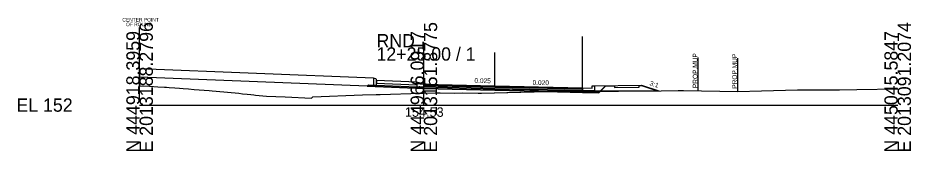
# Model space of a CAD drawing. Extents: x -26 to 163, y -10 to 7518.
# Drawn here: x -25.7 to 162.8, y 4490.3 to 4518.4 of the extents above; entities that cross this region are included whole.
import ezdxf

# ---------------------------------------------------------------- set-up
doc = ezdxf.new("R2010")
doc.units = 0
for name, color, linetype in [('Exist Cross Section Cell', 7, 'Continuous'), ('Exist XS Center Line Elevation Label', 7, 'Continuous'), ('Exist XS Ground Line', 7, 'Continuous'), ('Prop CMT Conc Surface', 7, 'Continuous'), ('Prop CMT Concrete Structures', 7, 'Continuous'), ('Prop CMT Pvmt Course 1', 7, 'Continuous'), ('Prop CMT Pvmt Course 1 CG', 7, 'Continuous'), ('Prop CMT Pvmt Course 2', 7, 'Continuous'), ('Prop CMT Pvmt Course 3', 7, 'Continuous'), ('Prop CMT Pvmt Surface', 7, 'Continuous'), ('Prop CMT Shear Line', 7, 'Continuous'), ('Prop CMT Shear Line Text', 7, 'Continuous'), ('Prop CMT Slope Grass', 7, 'Continuous'), ('Prop CMT Subgrade Earthwork', 7, 'Continuous'), ('Prop XS Earthwork Shape', 7, 'Continuous'), ('Prop XS Label Text', 7, 'Continuous'), ('Prop XS SE Text', 7, 'Continuous'), ('Prop XS Side Slope Text', 7, 'Continuous'), ('Scratch_Level_1', 7, 'Continuous')]:
    doc.layers.add(name, color=color, linetype=linetype)

msp = doc.modelspace()

# ---------------------------------------------------------------- linework, layer by layer
at = {"layer": 'Exist Cross Section Cell'}
for p, q in [((60, 4500), (60, 4512.16)), ((0, 4500), (60, 4500)), ((60, 4500), (160, 4500))]:
    msp.add_line(p, q, dxfattribs=at)
at = {"layer": 'Exist XS Ground Line'}
msp.add_lwpolyline([(0, 4504.05), (2.12, 4503.95), (3.88, 4503.85), (5.26, 4503.77), (5.67, 4503.74), (6.21, 4503.71), (7.45, 4503.63), (8.39, 4503.57), (9.23, 4503.5), (10.33, 4503.4), (11.52, 4503.3), (14.66, 4503.05), (15.33, 4502.99), (17.8, 4502.78), (18.56, 4502.71), (20.94, 4502.48), (21.7, 4502.39), (22.68, 4502.29), (23.49, 4502.21), (24.11, 4502.14), (24.47, 4502.11), (26.81, 4501.86), (30.69, 4501.71), (36.25, 4501.44), (36.55, 4501.77), (47.05, 4502.13), (49.93, 4502.24), (50.76, 4502.26), (59.46, 4502.52), (60, 4502.53), (62.37, 4502.57), (63.41, 4502.58), (66.44, 4502.54), (68.12, 4502.55), (71.45, 4502.54), (72.15, 4502.53), (86.04, 4502.86), (88.5, 4502.93), (98.29, 4502.93), (101.09, 4502.9), (110.08, 4503.02), (113.67, 4503.05), (114.78, 4503.04), (126.25, 4502.86), (131.26, 4502.97), (138.83, 4503.18), (147.75, 4503.22), (151.41, 4503.27), (160, 4503.43)], dxfattribs=at)
at = {"layer": 'Prop CMT Conc Surface'}
for points in [[(50, 4505.37), (49.96, 4505.47), (49.85, 4505.52), (49.34, 4505.7)], [(50, 4505.2), (50, 4505.37)], [(60, 4504.41), (59.25, 4504.43), (59.25, 4504.59), (58.5, 4504.84)], [(93.5, 4503.66), (95.49, 4503.53)], [(95.49, 4503.53), (95.5, 4504.03), (95.99, 4504.03)]]:
    msp.add_lwpolyline(points, dxfattribs=at)
at = {"layer": 'Prop CMT Concrete Structures'}
for points in [[(50, 4505.37), (49.96, 4505.47), (49.85, 4505.52), (49.34, 4505.7)], [(49.34, 4505.7), (49.34, 4504.2)], [(49.34, 4504.2), (50, 4504.2)], [(50, 4505.2), (50, 4505.37)], [(50, 4504.2), (50, 4505.2)], [(50, 4505.2), (50, 4504.62)], [(58.5, 4504.84), (50, 4505.19)], [(50, 4504.6), (58.5, 4504.26)], [(60, 4504.41), (59.25, 4504.43), (59.25, 4504.59), (58.5, 4504.84)], [(58.5, 4504.84), (58.5, 4503.86)], [(58.5, 4504.26), (58.5, 4504.84)], [(60, 4503.83), (60, 4504.41)], [(58.5, 4503.86), (60, 4503.83)], [(93.5, 4503.66), (95.49, 4503.53), (95.5, 4504.03), (95.99, 4504.03)], [(95.99, 4504.03), (95.99, 4503.01), (93.5, 4503.08)], [(93.5, 4503.08), (93.5, 4503.66)]]:
    msp.add_lwpolyline(points, dxfattribs=at)
at = {"layer": 'Prop CMT Pvmt Course 1'}
for points in [[(60, 4504.41), (75, 4504.03)], [(60, 4504.16), (60, 4504.41)], [(75, 4503.78), (60, 4504.16)], [(75, 4504.03), (93.5, 4503.66)], [(93.5, 4503.41), (75, 4503.78)], [(93.5, 4503.66), (93.5, 4503.41)]]:
    msp.add_lwpolyline(points, dxfattribs=at)
msp.add_lwpolyline([(60, 4504.16), (60, 4504.28), (60, 4504.28), (60, 4504.16)], close=True, dxfattribs=at)
at = {"layer": 'Prop CMT Pvmt Course 1 CG'}
for points in [[(60, 4503.49), (60, 4503.83)], [(93.5, 4503.08), (96.49, 4503), (96.83, 4502.66)], [(93.5, 4502.74), (93.5, 4503.08)], [(96.92, 4502.66), (93.5, 4502.74)]]:
    msp.add_lwpolyline(points, dxfattribs=at)
at = {"layer": 'Prop CMT Pvmt Course 2'}
for points in [[(60, 4503.83), (60, 4504.16)], [(60, 4504.16), (75, 4503.78)], [(75, 4503.45), (60, 4503.83)], [(75, 4503.78), (93.5, 4503.41)], [(93.51, 4503.08), (75, 4503.45)], [(93.5, 4503.41), (93.5, 4503.08)]]:
    msp.add_lwpolyline(points, dxfattribs=at)
at = {"layer": 'Prop CMT Pvmt Course 3'}
for points in [[(50, 4504.2), (58.5, 4503.86)], [(60, 4503.83), (75, 4503.45)], [(60, 4503.49), (60, 4503.83)], [(75, 4503.11), (60, 4503.49)], [(75, 4503.45), (93.51, 4503.08)], [(93.51, 4502.74), (75, 4503.11)], [(93.5, 4503.08), (93.5, 4502.74)]]:
    msp.add_lwpolyline(points, dxfattribs=at)
at = {"layer": 'Prop CMT Pvmt Surface'}
for points in [[(60, 4504.41), (75, 4504.03)], [(75, 4504.03), (93.5, 4503.66)]]:
    msp.add_lwpolyline(points, dxfattribs=at)
at = {"layer": 'Prop CMT Shear Line'}
msp.add_line((0, 4501.35), (0, 4516.35), dxfattribs=at)
at = {"layer": 'Prop CMT Slope Grass'}
for p, q in [((49.34, 4505.69), (0, 4507.66)), ((48.06, 4503.97), (0, 4505.89))]:
    msp.add_line(p, q, dxfattribs=at)
msp.add_lwpolyline([(95.99, 4504.03), (105.93, 4504.23), (109.59, 4503.01)], dxfattribs=at)
at = {"layer": 'Prop CMT Subgrade Earthwork'}
for p, q in [((0, 4507.66), (0, 4504.05)), ((48.34, 4504.24), (48.06, 4503.97))]:
    msp.add_line(p, q, dxfattribs=at)
for points in [[(48.34, 4504.24), (49.34, 4504.2)], [(93.5, 4502.74), (96.92, 4502.66), (98.33, 4504.08)], [(48.06, 4503.97), (60, 4503.49)], [(60, 4503.49), (75, 4503.11)], [(75, 4503.11), (93.51, 4502.74)]]:
    msp.add_lwpolyline(points, dxfattribs=at)
at = {"layer": 'Prop XS Earthwork Shape'}
for points in [[(63.41, 4502.58), (66.44, 4502.54), (68.12, 4502.55), (71.45, 4502.54), (72.15, 4502.53), (85.63, 4502.85), (60, 4503.49), (48.06, 4503.97), (0, 4505.89), (0, 4504.05), (2.12, 4503.95), (3.88, 4503.85), (5.26, 4503.77), (5.67, 4503.74), (6.21, 4503.71), (7.45, 4503.63), (8.39, 4503.57), (9.23, 4503.5), (10.33, 4503.4), (11.52, 4503.3), (14.66, 4503.05), (15.33, 4502.99), (17.8, 4502.78), (18.56, 4502.71), (20.94, 4502.48), (21.7, 4502.39), (22.68, 4502.29), (23.49, 4502.21), (24.11, 4502.14), (24.47, 4502.11), (26.81, 4501.86), (30.69, 4501.71), (36.25, 4501.44), (36.55, 4501.77), (47.05, 4502.13), (49.93, 4502.24), (50.76, 4502.26), (59.46, 4502.52), (60, 4502.53), (62.37, 4502.57)], [(105.93, 4504.14), (109.32, 4503.01), (101.09, 4502.9), (98.29, 4502.93), (97.28, 4502.93), (98.33, 4503.98), (100.24, 4504.03), (100.24, 4503.7), (105.43, 4503.8), (105.43, 4504.14)], [(96.91, 4502.57), (97.28, 4502.93), (95.99, 4502.93), (95.99, 4502.92), (95.53, 4502.93), (88.5, 4502.93), (86.04, 4502.86), (85.63, 4502.85), (93.5, 4502.65)], [(95.53, 4502.93), (95.99, 4502.93), (95.99, 4502.92)]]:
    msp.add_lwpolyline(points, close=True, dxfattribs=at)
at = {"layer": 'Prop XS Label Text'}
for p, q in [((117.84, 4510), (117.84, 4503)), ((126.19, 4509.86), (126.19, 4502.86))]:
    msp.add_line(p, q, dxfattribs=at)
at = {"layer": 'Scratch_Level_1'}
for p, q in [((93.5, 4503.57), (93.5, 4514.47)), ((75, 4504.03), (75, 4511.06))]:
    msp.add_line(p, q, dxfattribs=at)

# ---------------------------------------------------------------- texts
at = {"layer": 'Exist Cross Section Cell'}
for s, p in [('E 2013188.2796', (2.8, 4490)), ('E 2013151.8775', (62.8, 4490)), ('E 2013091.2074', (162.8, 4490)), ('N 444918.3959', (0, 4490)), ('N 444966.0917', (60, 4490)), ('N 445045.5847', (160, 4490))]:
    msp.add_text(s, height=2.8, rotation=90, dxfattribs=at).set_placement(p)
for s, p in [('RND', (50, 4512.16)), ('12+25.00 / 1', (50, 4509.36)), ('EL 152', (-26, 4498.6))]:
    msp.add_text(s, height=2.8, dxfattribs=at).set_placement(p)
at = {"layer": 'Exist XS Center Line Elevation Label'}
msp.add_text('154.53', height=2, dxfattribs=at).set_placement((55.99, 4497.53))
at = {"layer": 'Prop CMT Shear Line Text'}
for s, p in [('CENTER POINT', (-3.64, 4517.6)), ('OF ROUND', (-2.88, 4516.62))]:
    msp.add_text(s, height=0.75, dxfattribs=at).set_placement(p)
at = {"layer": 'Prop XS Label Text'}
for p in [(117.74, 4503.57), (126.09, 4503.44)]:
    msp.add_text('PROP.MUP', height=1, rotation=90, dxfattribs=at).set_placement(p)
at = {"layer": 'Prop XS SE Text'}
for s, p in [('0.025', (70.67, 4504.69)), ('0.020', (82.93, 4504.28))]:
    msp.add_text(s, height=1, rotation=358.5613, dxfattribs=at).set_placement(p)
at = {"layer": 'Prop XS Side Slope Text'}
msp.add_text('3:1', height=1, rotation=341.5651, dxfattribs=at).set_placement((107.56, 4504.22))

doc.saveas('drawing.dxf')
